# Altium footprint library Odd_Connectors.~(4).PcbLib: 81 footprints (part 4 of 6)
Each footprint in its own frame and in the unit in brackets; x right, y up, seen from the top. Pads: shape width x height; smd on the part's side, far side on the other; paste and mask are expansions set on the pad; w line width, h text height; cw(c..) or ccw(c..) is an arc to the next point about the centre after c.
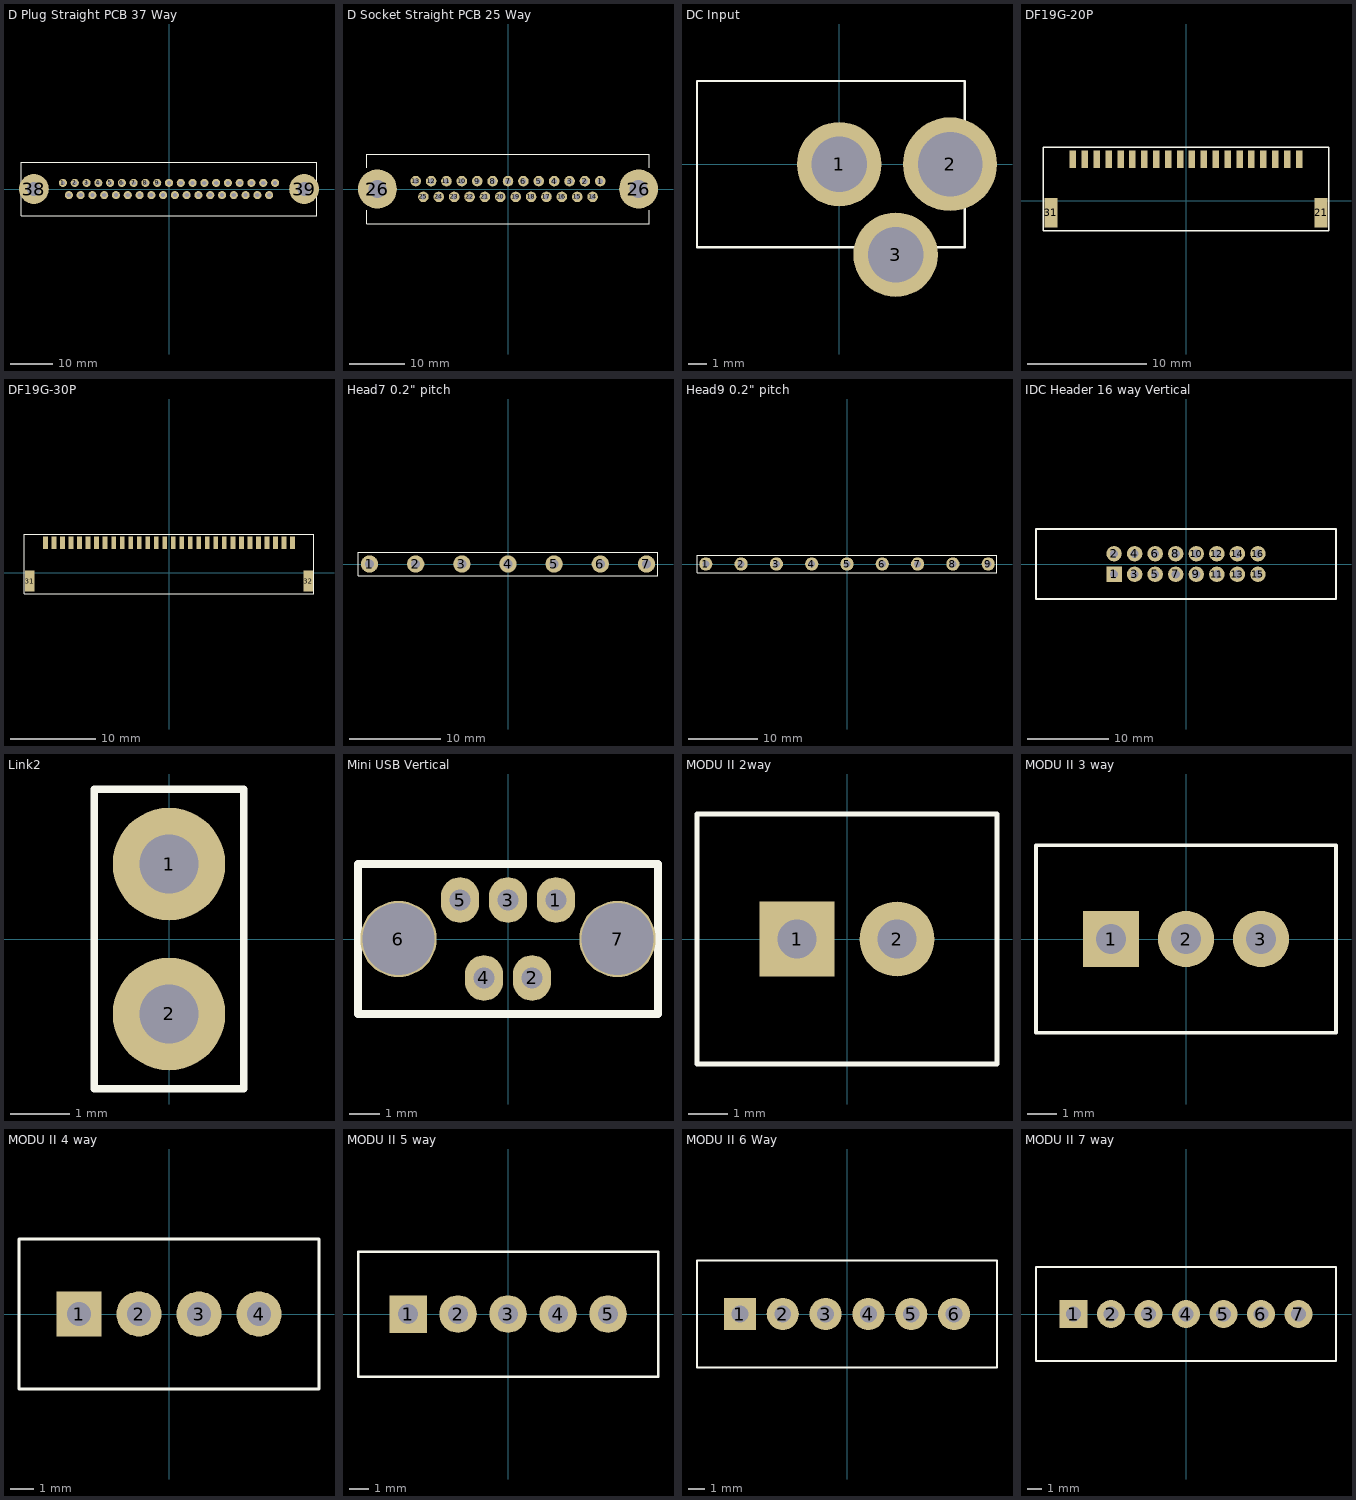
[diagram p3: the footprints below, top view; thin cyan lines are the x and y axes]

## D Plug Straight PCB 37 Way [mil] "D Plug Straight PCB 37 Way"
height 472.44
pads (39):
  round 75 hole 39.37: 1(-981,56) 2(-872,56) 3(-763,56) 4(-654,56) 5(-545,56) 6(-436,56) 7(-327,56) 8(-218,56) 9(-109,56) 10(0,56) 11(109,56) 12(218,56) 13(327,56) 14(436,56) 15(545,56) 16(654,56) 17(763,56) 18(872,56) 19(981,56) 20(-926.5,-56) 21(-817.5,-56) 22(-708.5,-56) 23(-599.5,-56) 24(-490.5,-56) 25(-381.5,-56) 26(-272.5,-56) 27(-163.5,-56) 28(-54.5,-56) 29(54.5,-56) 30(163.5,-56) 31(272.5,-56) 32(381.5,-56) 33(490.5,-56) 34(599.5,-56) 35(708.5,-56) 36(817.5,-56) 37(926.5,-56)
  round 275.59 hole 125.98: 38(-1250,0) 39(1250,0)
Top Overlay:
  lines w10: -1365,-247.05 -1365,247.05 1365,247.05 1365,-247.05 -1365,-247.05

## D Socket Straight PCB 25 Way [mil] "D socket Straight PCB 25 Way"
height 472.44
pads (27):
  round 75 hole 39.37 unplated: 1(654,56) 2(545,56) 3(436,56) 4(327,56) 5(218,56) 6(109,56) 7(0,56) 8(-109,56) 9(-218,56) 10(-327,56) 11(-436,56) 12(-545,56) 13(-654,56) 14(599.5,-56) 15(490.5,-56) 16(381.5,-56) 17(272.5,-56) 18(163.5,-56) 19(54.5,-56) 20(-54.5,-56) 21(-163.5,-56) 22(-272.5,-56) 23(-381.5,-56) 24(-490.5,-56) 25(-599.5,-56)
  round 275.59 hole 125.98 unplated: 26(-925,0) 26(925,0)
Top Overlay:
  lines w0.98: -1000,-247.05 -1000,-150 ; -1000,150 -1000,247.05 ; 1000,-247.05 1000,-150 ; 1000,150 1000,247.05
  lines w1: -1000,-247.05 1000,-247.05 ; -1000,247.05 1000,247.05

## DC Input [mm] "DC Power input, 2.1 or 2.5mm pin"
height 11
pads (3):
  round 4.572 hole 3: 1(0,0) 3(3.05,-4.9)
  round 5.08 hole 3.5: 2(6,0)
Top Overlay:
  lines w0.127: -7.7,-4.5 6.8,-4.5 6.8,4.5 -7.7,4.5 -7.7,-4.5

## DF19G-20P [mm] "Hirose 1mm pitch connector"
height 1.6
pads (22):
  rect 0.55x1.5 smd: 1(-9.5,3.5) 2(-8.5,3.5) 3(-7.5,3.5) 4(-6.5,3.5) 5(-5.5,3.5) 6(-4.5,3.5) 7(-3.5,3.5) 8(-2.5,3.5) 9(-1.5,3.5) 10(-0.5,3.5) 11(0.5,3.5) 12(1.5,3.5) 13(2.5,3.5) 14(3.5,3.5) 15(4.5,3.5) 16(5.5,3.5) 17(6.5,3.5) 18(7.5,3.5) 19(8.5,3.5) 20(9.5,3.5)
  rect 1.1x2.5 smd: 21(11.35,-1) 31(-11.35,-1)
Top Overlay:
  lines w0.127: -12,-2.5 -12,4.5 12,4.5 12,-2.5 -12,-2.5

## DF19G-30P [mm] "Hirose 1mm pitch connector"
height 1.6
pads (32):
  rect 0.55x1.5 smd: 1(-14.5,3.5) 2(-13.5,3.5) 3(-12.5,3.5) 4(-11.5,3.5) 5(-10.5,3.5) 6(-9.5,3.5) 7(-8.5,3.5) 8(-7.5,3.5) 9(-6.5,3.5) 10(-5.5,3.5) 11(-4.5,3.5) 12(-3.5,3.5) 13(-2.5,3.5) 14(-1.5,3.5) 15(-0.5,3.5) 16(0.5,3.5) 17(1.5,3.5) 18(2.5,3.5) 19(3.5,3.5) 20(4.5,3.5) 21(5.5,3.5) 22(6.5,3.5) 23(7.5,3.5) 24(8.5,3.5) 25(9.5,3.5) 26(10.5,3.5) 27(11.5,3.5) 28(12.5,3.5) 29(13.5,3.5) 30(14.5,3.5)
  rect 1.1x2.5 smd: 31(-16.35,-1) 32(16.35,-1)
Top Overlay:
  lines w0.127: -17,-2.5 17,-2.5 17,4.5 -17,4.5 -17,-2.5

## Head7 0.2" pitch [mm] "7 way header on 0.2\" pitch"
height 12.7
pads (7):
  round 1.905 hole 1: 1(-15.24,0) 2(-10.16,0) 3(-5.08,0) 4(0,0) 5(5.08,0) 6(10.16,0) 7(15.24,0)
Top Overlay:
  lines w0.127: -16.51,-1.27 -16.51,1.27 16.51,1.27 16.51,-1.27 -16.51,-1.27

## Head9 0.2" pitch [mm] "9 way header on 0.2\" pitch"
height 12.7
pads (9):
  round 1.905 hole 1: 1(-20.32,0) 2(-15.24,0) 3(-10.16,0) 4(-5.08,0) 5(0,0) 6(5.08,0) 7(10.16,0) 8(15.24,0) 9(20.32,0)
Top Overlay:
  lines w0.127: -21.59,-1.27 -21.59,1.27 21.59,1.27 21.59,-1.27 -21.59,-1.27

## IDC Header 16 way Vertical [mm] "IDC Header 16 way Vertical"
height 20
pads (16):
  rect 1.905x1.905 hole 1: 1(-8.89,-1.27)
  round 1.905 hole 1: 2(-8.89,1.27) 3(-6.35,-1.27) 4(-6.35,1.27) 5(-3.81,-1.27) 6(-3.81,1.27) 7(-1.27,-1.27) 8(-1.27,1.27) 9(1.27,-1.27) 10(1.27,1.27) 11(3.81,-1.27) 12(3.81,1.27) 13(6.35,-1.27) 14(6.35,1.27) 15(8.89,-1.27) 16(8.89,1.27)
Top Overlay:
  lines w0.254: -18.542,-4.318 -18.542,4.318 18.542,4.318 18.542,-4.318 -18.542,-4.318

## Link2 [mm] "2 pin link"
height 12
pads (2):
  round 1.905 hole 1: 1(0,1.27) 2(0,-1.27)
Top Overlay:
  lines w0.127: -1.27,-2.54 -1.27,2.54 1.27,2.54 1.27,-2.54 -1.27,-2.54

## Mini USB Vertical [mm]
pads (7):
  oval 1.27x1.524 hole 0.7: 1(1.6,1.3) 2(0.8,-1.3) 3(0,1.3) 4(-0.8,-1.3) 5(-1.6,1.3)
  round 2.54 hole 2.4: 6(-3.65,0) 7(3.65,0)
Top Overlay:
  lines w0.254: -5,-2.5 -5,2.5 5,2.5 5,-2.5 -5,-2.5

## MODU II 2way [mm] "Amp Modu ii headers"
height 15
pads (2):
  rect 1.905x1.905 hole 1: 1(-1.27,0)
  round 1.905 hole 1: 2(1.27,0)
Top Overlay:
  lines w0.127: -3.81,-3.175 3.81,-3.175 3.81,3.175 -3.81,3.175 -3.81,-3.175

## MODU II 3 way [mm] "Amp Modu ii headers"
height 15
pads (3):
  rect 1.905x1.905 hole 1: 1(-2.54,0)
  round 1.905 hole 1: 2(0,0) 3(2.54,0)
Top Overlay:
  lines w0.127: -5.08,-3.175 -5.08,3.175 5.08,3.175 5.08,-3.175 -5.08,-3.175

## MODU II 4 way [mm] "Amp Modu ii headers"
height 15
pads (4):
  rect 1.905x1.905 hole 1: 1(-3.81,0)
  round 1.905 hole 1: 2(-1.27,0) 3(1.27,0) 4(3.81,0)
Top Overlay:
  lines w0.127: -6.35,-3.175 -6.35,3.175 6.35,3.175 6.35,-3.175 -6.35,-3.175

## MODU II 5 way [mm] "Amp Modu ii headers"
height 15
pads (5):
  rect 1.905x1.905 hole 1: 1(-5.08,0)
  round 1.905 hole 1: 2(-2.54,0) 3(0,0) 4(2.54,0) 5(5.08,0)
Top Overlay:
  lines w0.127: -7.62,-3.175 -7.62,3.175 7.62,3.175 7.62,-3.175 -7.62,-3.175

## MODU II 6 Way [mm] "Amp Modu ii headers"
height 15
pads (6):
  rect 1.905x1.905 hole 1: 1(-6.35,0)
  round 1.905 hole 1: 2(-3.81,0) 3(-1.27,0) 4(1.27,0) 5(3.81,0) 6(6.35,0)
Top Overlay:
  lines w0.127: -8.89,-3.175 -8.89,3.175 8.89,3.175 8.89,-3.175 -8.89,-3.175

## MODU II 7 way [mm] "Amp Modu ii headers"
height 15
pads (7):
  rect 1.905x1.905 hole 1: 1(-7.62,0)
  round 1.905 hole 1: 2(-5.08,0) 3(-2.54,0) 4(0,0) 5(2.54,0) 6(5.08,0) 7(7.62,0)
Top Overlay:
  lines w0.127: -10.16,-3.175 10.16,-3.175 10.16,3.175 -10.16,3.175 -10.16,-3.175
